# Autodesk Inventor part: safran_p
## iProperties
Shininess: 64.0
Length Units: 11269
Angle Units: 11279
Time Units: 11290
Mass Units: 11283
Length Display Precision: 3
Angle Display Precision: 2
Compacted: True
Part Number: safran_p
Document SubType Name: Modeling
Created: 2004-06
Material: Par défaut
Designer: David
Density: 0.0
Volumn: 0.0
Area: 0.0
PropertySet Name: Model Information
Control State: 0
Master: False
Checked Out: False
Author: David
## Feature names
1. Extrusion1
